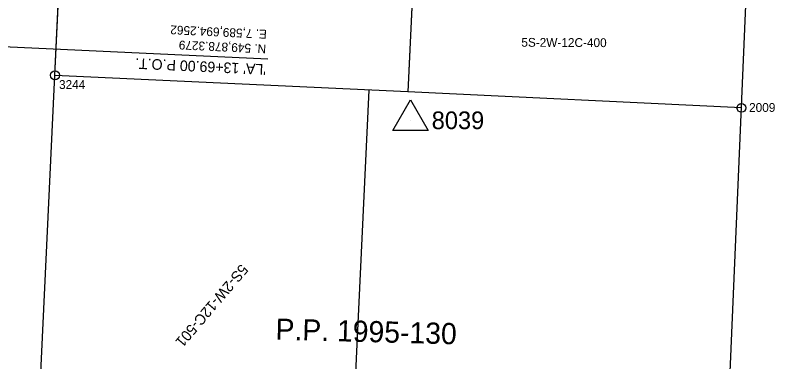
# Model space of a CAD drawing. Extents: x 7581380 to 7602708, y 543740 to 556109.
# Drawn here: x 7589701 to 7590131.1, y 549699.7 to 549896 of the extents above; entities that cross this region are included whole.
import ezdxf

# ---------------------------------------------------------------- set-up
doc = ezdxf.new("R2010")
doc.units = 0
for name, color, linetype in [('E_SURV_ALIGN_MinorTx', 7, 'Continuous'), ('E_SURV_BNDRY_CROW', 7, 'Continuous'), ('E_SURV_BNDRY_Property', 7, 'Continuous'), ('E_SURV_BNDRY_SubdivisionTx', 7, 'Continuous'), ('E_Surv_Bndry_Tax_Lot', 7, 'Continuous'), ('E_SURV_MON_FdMon', 7, 'Continuous'), ('E_SURV_MON_FdMonTx', 7, 'Continuous'), ('E_SURV_NTW_SetNtwPt', 7, 'Continuous'), ('E_SURV_NTW_SetNtwPtTx', 7, 'Continuous'), ('P_RW_ALIGN_SecTx', 7, 'Continuous'), ('P_RW_ALIGN_SecTxCoor', 7, 'Continuous'), ('P_RW_FILE_AreaShapeRemain', 7, 'Continuous')]:
    doc.layers.add(name, color=color, linetype=linetype)

msp = doc.modelspace()

# ---------------------------------------------------------------- linework, layer by layer
at = {"layer": 'E_SURV_ALIGN_MinorTx'}
msp.add_lwpolyline([(7589694.26, 549878.31), (7589844.09, 549871.21)], dxfattribs=at)
at = {"layer": 'E_SURV_BNDRY_CROW'}
for p, q in [((7589706.72, 549507.46), (7589739.37, 550196.53)), ((7590071.22, 548878.85), (7590126.46, 550178.14))]:
    msp.add_line(p, q, dxfattribs=at)
msp.add_circle((7589723.55, 549861.94), 2.5, dxfattribs=at)
at = {"layer": 'E_SURV_BNDRY_Property'}
for p, q in [((7589923.25, 549852.55), (7589723.51, 549861.91)), ((7589901.26, 549853.58), (7589891.76, 549653.67))]:
    msp.add_line(p, q, dxfattribs=at)
for points in [[(7589939.21, 550187.04), (7589923.25, 549852.55)], [(7590112.24, 549843.58), (7589923.25, 549852.56)]]:
    msp.add_lwpolyline(points, dxfattribs=at)
at = {"layer": 'E_SURV_MON_FdMon'}
msp.add_circle((7590112.18, 549843.49), 2.5, dxfattribs=at)
at = {"layer": 'E_SURV_NTW_SetNtwPt'}
for p, q in [((7589914.82, 549830.7), (7589924.82, 549848.02)), ((7589924.82, 549848.02), (7589934.82, 549830.7)), ((7589924.82, 549836.47), (7589924.82, 549836.47)), ((7589934.82, 549830.7), (7589914.82, 549830.7))]:
    msp.add_line(p, q, dxfattribs=at)
at = {"layer": 'P_RW_ALIGN_SecTx'}
msp.add_lwpolyline([(7589694.26, 549878.33), (7589844.09, 549871.23)], dxfattribs=at)
at = {"layer": 'P_RW_FILE_AreaShapeRemain'}
msp.add_lwpolyline([(7589738.09, 550169.58), (7589751.26, 550184.98), (7589766.74, 550194.76), (7589797.71, 550193.29), (7589846.12, 550179.63), (7589938.5, 550172.17), (7589923.25, 549852.55), (7589723.51, 549861.91), (7589726.12, 549916.86), (7589743.09, 549937.08), (7589747.8, 549951.88), (7589748.46, 549965.86), (7589743.32, 549984.12), (7589730.04, 549999.77)], close=True, dxfattribs=at)

# ---------------------------------------------------------------- texts
at = {"layer": 'E_SURV_BNDRY_SubdivisionTx'}
msp.add_text('P.P. 1995-130', height=12, rotation=358.4999, dxfattribs=at).set_placement((7589848.29, 549712.28))
at = {"layer": 'E_Surv_Bndry_Tax_Lot'}
for s, height, rotation, p in [('5S-2W-12C-400', 5, 359.7425, (7589987.56, 549878.13)), ('5S-2W-12C-501', 6, 229.598, (7589828.88, 549755.49))]:
    msp.add_text(s, height=height, rotation=rotation, dxfattribs=at).set_placement(p)
at = {"layer": 'E_SURV_MON_FdMonTx'}
for s, p in [('3244', (7589725.82, 549854.21)), ('2009', (7590116.53, 549841.23))]:
    msp.add_text(s, height=5, dxfattribs=at).set_placement(p)
at = {"layer": 'E_SURV_NTW_SetNtwPtTx'}
msp.add_text('8039', height=10, dxfattribs=at).set_placement((7589936.82, 549831.47))
at = {"layer": 'P_RW_ALIGN_SecTxCoor'}
for s, height, p in [('E. 7,589,694.2562', 5, (7589843.57, 549887.64)), ('N. 549,878.3279', 5, (7589843.18, 549879.31)), ("'LA' 13+69.00 P.O.T.", 6, (7589843.13, 549868.17))]:
    msp.add_text(s, height=height, rotation=177.2872, dxfattribs=at).set_placement(p)

doc.saveas('drawing.dxf')
